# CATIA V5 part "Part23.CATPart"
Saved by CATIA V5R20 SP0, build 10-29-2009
Part number: JT12.5x2.5
Revision: ANY
Definition: UNKNOWN
Nomenclature: JT12.5x2.5
Source: Unknown
Bounding box of the stored display mesh (mm): x -8.75 to 8.75, y -1.25 to 1.25, z -8.75 to 8.75
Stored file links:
  C:\Users\Utente\Desktop\IO LAVORO\3D X SITO CF\CUMSA\3D files SA\SA 200018\Part23.CATPart
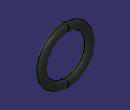
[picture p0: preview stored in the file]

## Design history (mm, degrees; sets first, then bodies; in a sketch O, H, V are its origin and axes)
Body1 "Revolución1" (main body)
  Solid1: solid without history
